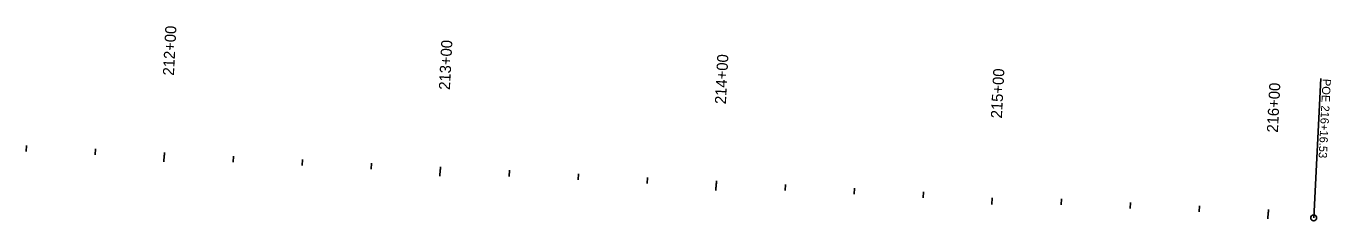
# Model space of a CAD drawing. Extents: x 20499876 to 20505320, y 7953544 to 7954108.
# Drawn here: x 20504848.1 to 20505320.3, y 7953617.9 to 7953688.2 of the extents above; entities that cross this region are included whole.
import ezdxf

# ---------------------------------------------------------------- set-up
doc = ezdxf.new("R2010")
doc.units = 0
for name, color, linetype in [('Draft_7', 7, 'Continuous'), ('PS_CONST', 7, 'Continuous'), ('Revetment', 7, 'Continuous')]:
    doc.layers.add(name, color=color, linetype=linetype)

msp = doc.modelspace()

# ---------------------------------------------------------------- linework, layer by layer
at = {"layer": 'Draft_7'}
for p, q in [((20504848.15, 7953642.96), (20504848.26, 7953645.14)), ((20504873.11, 7953641.67), (20504873.23, 7953643.85)), ((20504898.14, 7953641.61), (20504898.02, 7953639.16)), ((20504923.05, 7953639.1), (20504923.16, 7953641.28)), ((20504948.01, 7953637.81), (20504948.13, 7953639.99)), ((20504972.98, 7953636.52), (20504973.09, 7953638.7)), ((20504998.01, 7953636.46), (20504997.89, 7953634.01)), ((20505022.91, 7953633.95), (20505023.03, 7953636.13)), ((20505047.88, 7953632.66), (20505047.99, 7953634.84)), ((20505072.85, 7953631.37), (20505072.96, 7953633.55)), ((20505097.88, 7953631.31), (20505097.75, 7953628.86)), ((20505122.78, 7953628.8), (20505122.89, 7953630.98)), ((20505147.75, 7953627.51), (20505147.86, 7953629.69)), ((20505172.72, 7953626.23), (20505172.83, 7953628.41)), ((20505197.75, 7953626.16), (20505197.62, 7953623.72)), ((20505222.65, 7953623.65), (20505222.76, 7953625.83)), ((20505247.62, 7953622.36), (20505247.73, 7953624.54)), ((20505272.58, 7953621.08), (20505272.7, 7953623.26)), ((20505297.61, 7953621.01), (20505297.49, 7953618.57))]:
    msp.add_line(p, q, dxfattribs=at)
at = {"layer": 'PS_CONST'}
for p, q in [((20504898.08, 7953640.38), (20504898.19, 7953642.57)), ((20504997.95, 7953635.24), (20504998.06, 7953637.42)), ((20505097.82, 7953630.09), (20505097.93, 7953632.27)), ((20505197.75, 7953626.16), (20505197.62, 7953623.72)), ((20505297.55, 7953619.79), (20505297.66, 7953621.97))]:
    msp.add_line(p, q, dxfattribs=at)
at = {"layer": 'Revetment'}
for p in [(20505314.06, 7953618.94), (20505316.66, 7953669.27)]:
    msp.add_line(p, (20505316.66, 7953669.27), dxfattribs=at)
msp.add_circle((20505314.06, 7953618.94), 1.07, dxfattribs=at)

# ---------------------------------------------------------------- texts
at = {"layer": 'Draft_7'}
for s, p in [('212+00', (20504901.63, 7953670.24)), ('213+00', (20505001.49, 7953665.09)), ('214+00', (20505101.36, 7953659.94)), ('215+00', (20505201.23, 7953654.79)), ('216+00', (20505301.1, 7953649.65))]:
    msp.add_text(s, height=4.008, rotation=87.0487, dxfattribs=at).set_placement(p)
at = {"layer": 'PS_CONST'}
msp.add_text('215+00', height=4.008, rotation=87.0487, dxfattribs=at).set_placement((20505201.23, 7953654.79))
at = {"layer": 'Revetment'}
for s, p in [('POE ', (20505317.31, 7953669.24)), ('216+16.53', (20505316.82, 7953659.62))]:
    msp.add_text(s, height=3, rotation=267.0487, dxfattribs=at).set_placement(p)

doc.saveas('drawing.dxf')
